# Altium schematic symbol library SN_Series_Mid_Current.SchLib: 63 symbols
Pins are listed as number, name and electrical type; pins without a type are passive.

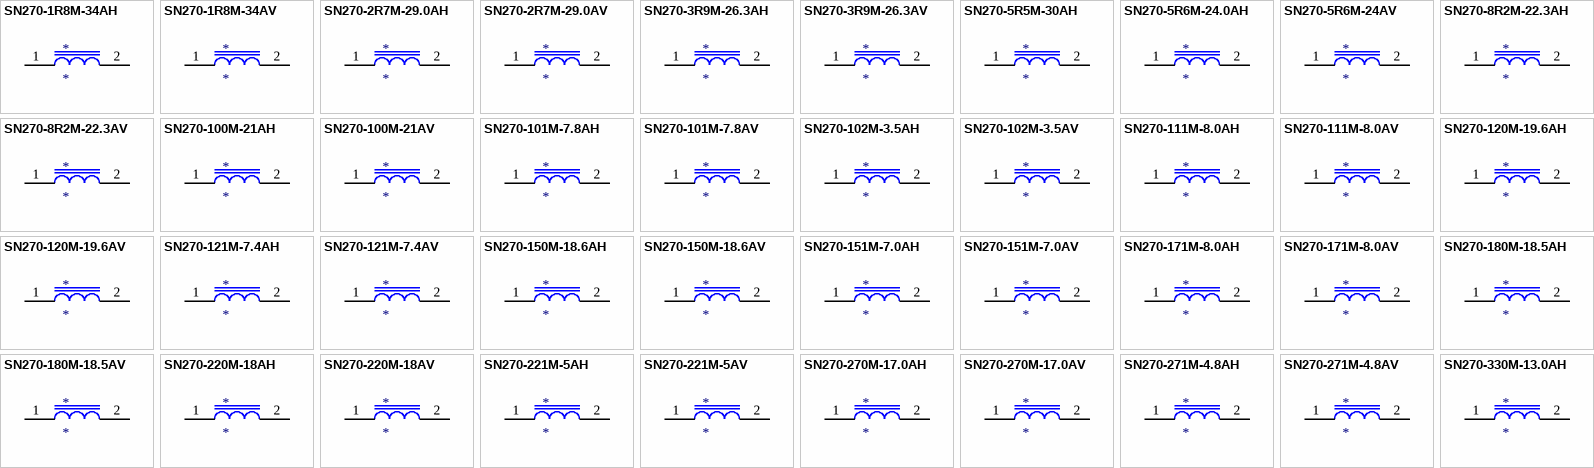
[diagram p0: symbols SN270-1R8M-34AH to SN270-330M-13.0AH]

## SN270-1R8M-34AH
designator *
POWER INDUCTOR 34 A, 1.85 uH, 2 mOhms, OD 36 mm, HT 20.32 mm; Manufacturer #1: CWS; Current: 34 A; DCR: 2 mOhms; Inductance: 1.85 uH; OD: 36 mm
footprint SN270-1R8M-34AH
pins: 1, 2

## SN270-1R8M-34AV
designator *
POWER INDUCTOR 34 A, 1.85 uH, 2 mOhms, OD 36 mm, HT 20.32 mm; Manufacturer #1: CWS; Current: 34 A; DCR: 2 mOhms; Inductance: 1.85 uH; OD: 36 mm
footprint SN270-1R8M-34AV
pins: 1, 2

## SN270-2R7M-29.0AH
designator *
POWER INDUCTOR 29 A, 2.7 uH, 2 mOhms, OD 22.86 mm, HT 10.16 mm; Manufacturer #1: CWS; Current: 29 A; DCR: 2 mOhms; Inductance: 2.7 uH
footprint SN270-2R7M-29.0AH
pins: 1, 2

## SN270-2R7M-29.0AV
designator *
POWER INDUCTOR 29 A, 2.7 uH, 2 mOhms, OD 22.86 mm, HT 10.16 mm; Manufacturer #1: CWS; Current: 29 A; DCR: 2 mOhms; Inductance: 2.7 uH
footprint SN270-2R7M-29.0AV
pins: 1, 2

## SN270-3R9M-26.3AH
designator *
POWER INDUCTOR 26.3 A, 3.9 uH, 2 mOhms, OD 35 mm, HT 19.05 mm; Manufacturer #1: CWS; Current: 26.3 A; DCR: 2 mOhms; Inductance: 3.9 uH; OD: 35 mm
footprint SN270-3R9M-26.3AH
pins: 1, 2

## SN270-3R9M-26.3AV
designator *
POWER INDUCTOR 26.3 A, 3.9 uH, 2 mOhms, OD 35 mm, HT 19.05 mm; Manufacturer #1: CWS; Current: 26.3 A; DCR: 2 mOhms; Inductance: 3.9 uH; OD: 35 mm
footprint SN270-3R9M-26.3AV
pins: 1, 2

## SN270-5R5M-30AH
designator *
POWER INDUCTOR 30 A, 5.5 uH, 3.5 mOhms, OD 36 mm, HT 22 mm; Manufacturer #1: CWS; Current: 30 A; Inductance: 5.5 uH; OD: 36 mm
footprint SN270-5R5M-30AH
pins: 1, 2

## SN270-5R6M-24.0AH
designator *
POWER INDUCTOR 24 A, 5.6 uH, 4 mOhms, OD 22.86 mm, HT 10.16 mm; Manufacturer #1: CWS; Current: 24 A; DCR: 4 mOhms; Inductance: 5.6 uH
footprint SN270-5R6M-24.0AH
pins: 1, 2

## SN270-5R6M-24AV
designator *
POWER INDUCTOR 24 A, 5.6 uH, 4 mOhms, OD 22.86 mm, HT 10.16 mm; Manufacturer #1: CWS; Current: 24 A; DCR: 4 mOhms; Inductance: 5.6 uH
footprint SN270-5R6M-24AV
pins: 1, 2

## SN270-8R2M-22.3AH
designator *
POWER INDUCTOR 22.3 A, 8.2 uH, 4.5 mOhms, OD 32.5 mm, HT 17.4 mm; Manufacturer #1: CWS; Current: 22.3 A; Inductance: 8.2 uH; OD: 32.5 mm
footprint SN270-8R2M-22.3AH
pins: 1, 2

## SN270-8R2M-22.3AV
designator *
POWER INDUCTOR 22.3 A, 8.2 uH, 4.5 mOhms, OD 32.5 mm, HT 17.4 mm; Manufacturer #1: CWS; Current: 22.3 A; Inductance: 8.2 uH; OD: 32.5 mm
footprint SN270-8R2M-22.3AV
pins: 1, 2

## SN270-100M-21AH
designator *
POWER INDUCTOR 21 A, 10 uH, 4.5 mOhms, OD 22.86 mm, HT 10.16 mm; Manufacturer #1: CWS; Current: 21 A; Inductance: 10 uH
footprint SN270-100M-21AH
pins: 1, 2

## SN270-100M-21AV
designator *
POWER INDUCTOR 21 A, 10 uH, 4.5 mOhms, OD 22.86 mm, HT 10.16 mm; Manufacturer #1: CWS; Current: 21 A; Inductance: 10 uH
footprint SN270-100M-21AV
pins: 1, 2

## SN270-101M-7.8AH
designator *
POWER INDUCTOR 7.8 A, 100 uH, 21 mOhms, OD 30.95 mm, HT 14.65 mm; Manufacturer #1: CWS; Current: 7.8 A; Inductance: 100 uH
footprint SN270-101M-7.8AH
pins: 1, 2

## SN270-101M-7.8AV
designator *
POWER INDUCTOR 7.8 A, 100 uH, 21 mOhms, OD 30.95 mm, HT 14.65 mm; Manufacturer #1: CWS; Current: 7.8 A; Inductance: 100 uH
footprint SN270-101M-7.8AV
pins: 1, 2

## SN270-102M-3.5AH
designator *
POWER INDUCTOR 3.5 A, 1000 uH, 93 mOhms, OD 31.5 mm, HT 18.3 mm; Manufacturer #1: CWS; Current: 3.5 A; Inductance: 1000 uH; OD: 31.5 mm
footprint SN270-102M-3.5AH
pins: 1, 2

## SN270-102M-3.5AV
designator *
POWER INDUCTOR 3.5 A, 1000 uH, 93 mOhms, OD 31.5 mm, HT 18.3 mm; Manufacturer #1: CWS; Current: 3.5 A; Inductance: 1000 uH; OD: 31.5 mm
footprint SN270-102M-3.5AV
pins: 1, 2

## SN270-111M-8.0AH
designator *
POWER INDUCTOR 8 A, 110 uH, 15 mOhms, OD 31.75 mm, HT 17.96 mm; Manufacturer #1: CWS; Current: 8 A; Inductance: 110 uH
footprint SN270-111M-8.0AH
pins: 1, 2

## SN270-111M-8.0AV
designator *
POWER INDUCTOR 8 A, 110 uH, 15 mOhms, OD 31.75 mm, HT 17.96 mm; Manufacturer #1: CWS; Current: 8 A; Inductance: 110 uH
footprint SN270-111M-8.0AV
pins: 1, 2

## SN270-120M-19.6AH
designator *
POWER INDUCTOR 19.6 A, 12 uH, 5 mOhms, OD 31 mm, HT 18.11 mm; Manufacturer #1: CWS; Current: 19.6 A; DCR: 5 mOhms; Inductance: 12 uH; OD: 31 mm
footprint SN270-120M-19.6AH
pins: 1, 2

## SN270-120M-19.6AV
designator *
POWER INDUCTOR 19.6 A, 12 uH, 5 mOhms, OD 31 mm, HT 18.11 mm; Manufacturer #1: CWS; Current: 19.6 A; DCR: 5 mOhms; Inductance: 12 uH; OD: 31 mm
footprint SN270-120M-19.6AV
pins: 1, 2

## SN270-121M-7.4AH
designator *
POWER INDUCTOR 7.4 A, 120 uH, 30 mOhms, OD 31.75 mm, HT 15.3 mm; Manufacturer #1: CWS; Current: 7.4 A; Inductance: 120 uH
footprint SN270-121M-7.4AH
pins: 1, 2

## SN270-121M-7.4AV
designator *
POWER INDUCTOR 7.4 A, 120 uH, 30 mOhms, OD 31.75 mm, HT 15.3 mm; Manufacturer #1: CWS; Current: 7.4 A; Inductance: 120 uH
footprint SN270-121M-7.4AV
pins: 1, 2

## SN270-150M-18.6AH
designator *
POWER INDUCTOR 18.6 A, 15 uH, 6 mOhms, OD 31.9 mm, HT 17.95 mm; Manufacturer #1: CWS; Current: 18.6 A; DCR: 6 mOhms; Inductance: 15 uH; OD: 31.9 mm
footprint SN270-150M-18.6AH
pins: 1, 2

## SN270-150M-18.6AV
designator *
POWER INDUCTOR 18.6 A, 15 uH, 6 mOhms, OD 31.9 mm, HT 17.95 mm; Manufacturer #1: CWS; Current: 18.6 A; DCR: 6 mOhms; Inductance: 15 uH; OD: 31.9 mm
footprint SN270-150M-18.6AV
pins: 1, 2

## SN270-151M-7.0AH
designator *
POWER INDUCTOR 7 A, 150 uH, 30 mOhms, OD 31.17 mm, HT 14.59 mm; Manufacturer #1: CWS; Current: 7 A; Inductance: 150 uH
footprint SN270-151M-7.0AH
pins: 1, 2

## SN270-151M-7.0AV
designator *
POWER INDUCTOR 7 A, 150 uH, 30 mOhms, OD 31.17 mm, HT 14.59 mm; Manufacturer #1: CWS; Current: 7 A; Inductance: 150 uH
footprint SN270-151M-7.0AV
pins: 1, 2

## SN270-171M-8.0AH
designator *
POWER INDUCTOR 8 A, 170 uH, 20 mOhms, OD 32 mm, HT 17.78 mm; Manufacturer #1: CWS; Current: 8 A; Inductance: 170 uH; OD: 32 mm
footprint SN270-171M-8.0AH
pins: 1, 2

## SN270-171M-8.0AV
designator *
POWER INDUCTOR 8 A, 170 uH, 20 mOhms, OD 32 mm, HT 17.78 mm; Manufacturer #1: CWS; Current: 8 A; Inductance: 170 uH; OD: 32 mm
footprint SN270-171M-8.0AV
pins: 1, 2

## SN270-180M-18.5AH
designator *
POWER INDUCTOR 18.5 A, 18 uH, 5 mOhms, OD 32.4 mm, HT 17.3 mm; Manufacturer #1: CWS; Current: 18.5 A; DCR: 5 mOhms; Inductance: 18 uH; OD: 32.4 mm
footprint SN270-180M-18.5AH
pins: 1, 2

## SN270-180M-18.5AV
designator *
POWER INDUCTOR 18.5 A, 18 uH, 6 mOhms, OD 32.4 mm, HT 17.3 mm; Manufacturer #1: CWS; Current: 18.5 A; DCR: 6 mOhms; Inductance: 18 uH; OD: 32.4 mm
footprint SN270-180M-18.5AV
pins: 1, 2

## SN270-220M-18AH
designator *
POWER INDUCTOR 18 A, 22 uH, 4 mOhms, OD 33.15 mm, HT 16.16 mm; Manufacturer #1: CWS; Current: 18 A; DCR: 4 mOhms; Inductance: 22 uH
footprint SN270-220M-18AH
pins: 1, 2

## SN270-220M-18AV
designator *
POWER INDUCTOR 18 A, 22 uH, 4 mOhms, OD 33.15 mm, HT 16.16 mm; Manufacturer #1: CWS; Current: 18 A; DCR: 4 mOhms; Inductance: 22 uH
footprint SN270-220M-18AV
pins: 1, 2

## SN270-221M-5AH
designator *
POWER INDUCTOR 5 A, 220 uH, 40 mOhms, OD 30.62 mm, HT 14.4 mm; Manufacturer #1: CWS; Current: 5 A; Inductance: 220 uH
footprint SN270-221M-5AH
pins: 1, 2

## SN270-221M-5AV
designator *
POWER INDUCTOR 5 A, 220 uH, 40 mOhms, OD 30.62 mm, HT 14.4 mm; Manufacturer #1: CWS; Current: 5 A; Inductance: 220 uH
footprint SN270-221M-5AV
pins: 1, 2

## SN270-270M-17.0AH
designator *
POWER INDUCTOR 17 A, 27 uH, 7 mOhms, OD 33.53 mm, HT 17.53 mm; Manufacturer #1: CWS; Current: 17 A; DCR: 7 mOhms; Inductance: 27 uH
footprint SN270-270M-17.0AH
pins: 1, 2

## SN270-270M-17.0AV
designator *
POWER INDUCTOR 17 A, 27 uH, 7 mOhms, OD 33.53 mm, HT 17.53 mm; Manufacturer #1: CWS; Current: 17 A; DCR: 7 mOhms; Inductance: 27 uH
footprint SN270-270M-17.0AV
pins: 1, 2

## SN270-271M-4.8AH
designator *
POWER INDUCTOR 4.8 A, 270 uH, 55 mOhms, OD 31.75 mm, HT 15.3 mm; Manufacturer #1: CWS; Current: 4.8 A; Inductance: 270 uH
footprint SN270-271M-4.8AH
pins: 1, 2

## SN270-271M-4.8AV
designator *
POWER INDUCTOR 4.8 A, 270 uH, 55 mOhms, OD 31.75 mm, HT 15.3 mm; Manufacturer #1: CWS; Current: 4.8 A; Inductance: 270 uH
footprint SN270-271M-4.8AV
pins: 1, 2

## SN270-330M-13.0AH
designator *
POWER INDUCTOR 13 A, 33 uH, 7 mOhms, OD 33.5 mm, HT 17.95 mm; Manufacturer #1: CWS; Current: 13 A; DCR: 7 mOhms; Inductance: 33 uH; OD: 33.5 mm
footprint SN270-330M-13.0AH
pins: 1, 2

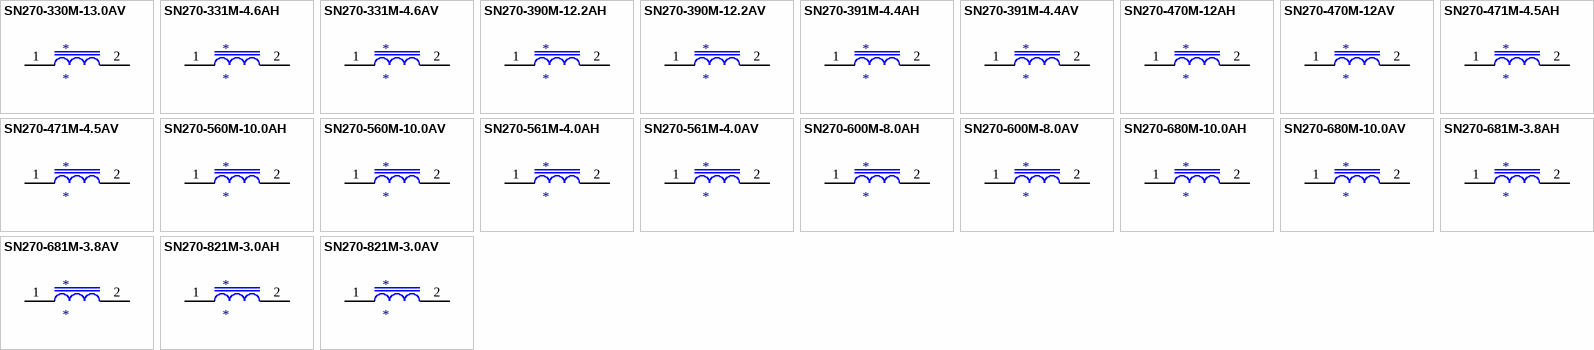
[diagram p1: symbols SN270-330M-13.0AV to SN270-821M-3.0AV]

## SN270-330M-13.0AV
designator *
POWER INDUCTOR 13 A, 33 uH, 7 mOhms, OD 33.5 mm, HT 17.95 mm; Manufacturer #1: CWS; Current: 13 A; DCR: 7 mOhms; Inductance: 33 uH; OD: 33.5 mm
footprint SN270-330M-13.0AV
pins: 1, 2

## SN270-331M-4.6AH
designator *
POWER INDUCTOR 4.6 A, 330 uH, 60 mOhms, OD 30.63 mm, HT 16.51 mm; Manufacturer #1: CWS; Current: 4.6 A; Inductance: 330 uH
footprint SN270-331M-4.6AH
pins: 1, 2

## SN270-331M-4.6AV
designator *
POWER INDUCTOR 4.6 A, 330 uH, 60 mOhms, OD 30.63 mm, HT 16.51 mm; Manufacturer #1: CWS; Current: 4.6 A; Inductance: 330 uH
footprint SN270-331M-4.6AV
pins: 1, 2

## SN270-390M-12.2AH
designator *
POWER INDUCTOR 12.2 A, 39 uH, 6 mOhms, OD 33 mm, HT 16 mm; Manufacturer #1: CWS; Current: 12.2 A; DCR: 6 mOhms; Inductance: 39 uH; OD: 33 mm
footprint SN270-390M-12.2AH
pins: 1, 2

## SN270-390M-12.2AV
designator *
POWER INDUCTOR 12.2 A, 39 uH, 6 mOhms, OD 33 mm, HT 16 mm; Manufacturer #1: CWS; Current: 12.2 A; DCR: 6 mOhms; Inductance: 39 uH; OD: 33 mm
footprint SN270-390M-12.2AV
pins: 1, 2

## SN270-391M-4.4AH
designator *
POWER INDUCTOR 4.4 A, 390 uH, 65 mOhms, OD 31.75 mm, HT 15.25 mm; Manufacturer #1: CWS; Current: 4.4 A; Inductance: 390 uH
footprint SN270-391M-4.4AH
pins: 1, 2

## SN270-391M-4.4AV
designator *
POWER INDUCTOR 4.4 A, 390 uH, 65 mOhms, OD 31.75 mm, HT 15.25 mm; Manufacturer #1: CWS; Current: 4.4 A; Inductance: 390 uH
footprint SN270-391M-4.4AV
pins: 1, 2

## SN270-470M-12AH
designator *
POWER INDUCTOR 12 A, 47 uH, 8 mOhms, OD 32.22 mm, HT 16.63 mm; Manufacturer #1: CWS; Current: 12 A; DCR: 8 mOhms; Inductance: 47 uH
footprint SN270-470M-12AH
pins: 1, 2

## SN270-470M-12AV
designator *
POWER INDUCTOR 12 A, 47 uH, 8 mOhms, OD 32.22 mm, HT 16.63 mm; Manufacturer #1: CWS; Current: 12 A; DCR: 8 mOhms; Inductance: 47 uH
footprint SN270-470M-12AV
pins: 1, 2

## SN270-471M-4.5AH
designator *
POWER INDUCTOR 4.5 A, 470 uH, 63 mOhms, OD 30.95 mm, HT 15.8 mm; Manufacturer #1: CWS; Current: 4.5 A; Inductance: 470 uH
footprint SN270-471M-4.5AH
pins: 1, 2

## SN270-471M-4.5AV
designator *
POWER INDUCTOR 4.5 A, 470 uH, 63 mOhms, OD 30.95 mm, HT 15.8 mm; Manufacturer #1: CWS; Current: 4.5 A; Inductance: 470 uH
footprint SN270-471M-4.5AV
pins: 1, 2

## SN270-560M-10.0AH
designator *
POWER INDUCTOR 10 A, 56 uH, 13 mOhms, OD 31.75 mm, HT 15.36 mm; Manufacturer #1: CWS; Current: 10 A; Inductance: 56 uH
footprint SN270-560M-10.0AH
pins: 1, 2

## SN270-560M-10.0AV
designator *
POWER INDUCTOR 10 A, 56 uH, 13 mOhms, OD 31.75 mm, HT 15.36 mm; Manufacturer #1: CWS; Current: 10 A; Inductance: 56 uH
footprint SN270-560M-10.0AV
pins: 1, 2

## SN270-561M-4.0AH
designator *
POWER INDUCTOR 4 A, 560 uH, 75 mOhms, OD 31.5 mm, HT 15.71 mm; Manufacturer #1: CWS; Current: 4 A; Inductance: 560 uH; OD: 31.5 mm
footprint SN270-561M-4.0AH
pins: 1, 2

## SN270-561M-4.0AV
designator *
POWER INDUCTOR 4 A, 560 uH, 75 mOhms, OD 31.5 mm, HT 15.71 mm; Manufacturer #1: CWS; Current: 4 A; Inductance: 560 uH; OD: 31.5 mm
footprint SN270-561M-4.0AV
pins: 1, 2

## SN270-600M-8.0AH
designator *
POWER INDUCTOR 8 A, 60 uH, 15 mOhms, OD 33 mm, HT 17.78 mm; Manufacturer #1: CWS; Current: 8 A; Inductance: 60 uH; OD: 33 mm
footprint SN270-600M-8.0AH
pins: 1, 2

## SN270-600M-8.0AV
designator *
POWER INDUCTOR 8 A, 60 uH, 15 mOhms, OD 33 mm, HT 17.78 mm; Manufacturer #1: CWS; Current: 8 A; Inductance: 60 uH; OD: 33 mm
footprint SN270-600M-8.0AV
pins: 1, 2

## SN270-680M-10.0AH
designator *
POWER INDUCTOR 10 A, 68 uH, 13 mOhms, OD 31.75 mm, HT 15.87 mm; Manufacturer #1: CWS; Current: 10 A; Inductance: 68 uH
footprint SN270-680M-10.0AH
pins: 1, 2

## SN270-680M-10.0AV
designator *
POWER INDUCTOR 10 A, 68 uH, 13 mOhms, OD 31.75 mm, HT 15.87 mm; Manufacturer #1: CWS; Current: 10 A; Inductance: 68 uH
footprint SN270-680M-10.0AV
pins: 1, 2

## SN270-681M-3.8AH
designator *
POWER INDUCTOR 3.8 A, 680 uH, 83 mOhms, OD 33.02 mm, HT 16.51 mm; Manufacturer #1: CWS; Current: 3.8 A; Inductance: 680 uH
footprint SN270-681M-3.8AH
pins: 1, 2

## SN270-681M-3.8AV
designator *
POWER INDUCTOR 3.8 A, 680 uH, 83 mOhms, OD 33.02 mm, HT 16.51 mm; Manufacturer #1: CWS; Current: 3.8 A; Inductance: 680 uH
footprint SN270-681M-3.8AV
pins: 1, 2

## SN270-821M-3.0AH
designator *
POWER INDUCTOR 3 A, 820 uH, 105 mOhms, OD 31.75 mm, HT 16.51 mm; Manufacturer #1: CWS; Current: 3 A; Inductance: 820 uH
footprint SN270-821M-3.0AH
pins: 1, 2

## SN270-821M-3.0AV
designator *
POWER INDUCTOR 3 A, 820 uH, 105 mOhms, OD 31.75 mm, HT 16.51 mm; Manufacturer #1: CWS; Current: 3 A; Inductance: 820 uH
footprint SN270-821M-3.0AV
pins: 1, 2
